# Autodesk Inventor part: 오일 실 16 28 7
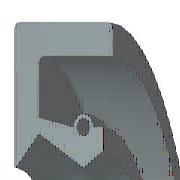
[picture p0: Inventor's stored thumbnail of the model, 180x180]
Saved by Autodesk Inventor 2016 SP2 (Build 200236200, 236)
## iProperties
Created: 2012-02
Part Number: 오일 실 16 28 7
Material: 고무
Description: 오일-실
Document SubType Name: Modeling
Standard: KS B 2804
Designer: mduedu
Standards Organization: KS
Language: ko-KR
Size Designation: D - 16 28 7
Categories: <MemberInstance><Categories><Category DisplayName="샤프트 부품" InternalName="7f7aeb1f-a693-4053-b835-cee3144e0d98" Mnemonic="SHFT"><Category DisplayName="실링" Intern
Density: 0.93 g/cm^3
Appearance: 고무 - 검은색 - 버전 1.1
IsCustomPart: 1
Author: mduedu
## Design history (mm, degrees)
revolve "본체" stored, may be unused: angle "d17" = 90 deg
revolve "스프링1" stored, may be unused: angle "d18" = 90 deg
fillet "모깎기3" dims "d43" = 0.5
body "Solid1"
sketch "스케치1"
  geometry: L1 (0, 14)-(7, 14); L2 (7, 12.25)-(1.75, 12.25); L3 (1.75, 9.75)-(4.9, 8); L4 (4.9, 8)-(0, 8); L5 (0, 0)-(9.586, 0) reference; L6 (4.9, 8)-(6.3, 8.875); L7 (0, 18)-(0, -3) reference; L8 (-1.941, 0)-(11.507, 0) reference; L9 (4.2, 10.1)-(1.75, 10.59); L10 (1.75, 10.59)-(1.75, 12.25); L11 (0, 14)-(0, 8.088); L12 (4.9, 8)-(0, 8); L13 (1.75, 9.75)-(0.152, 8.028); L14 (7, 14)-(7, 12.25); L15 (5.6, 10.1)-(6.3, 10.1); L16 (6.3, 10.1)-(6.3, 8.875); C1 r 0.455 at (4.9, 10.1); A1 r 0.7 centre (4.9, 10.1) between (5.6, 10.1) and (4.2, 10.1); A2 r 0.088 centre (0.088, 8.088) between (0, 8.088) and (0.152, 8.028); 1 further point
  constraints: 28 end point, 5 horizontal alignment, 5 point on line, 4 point on circle, 4 vertical alignment, 3 centre point, 3 tangent, 2 collinear, 2 horizontal, 2 perpendicular, 1 coincident, 1 parallel
  dimensions: "d0" = 28 diameter of L1 L5 (= SD2); "d1" = 1.75 distance of L1.end L2.start (= SD); "d2" = 0.91 diameter of C1 (= SPDI); "d3" = 1.4 diameter of A1 (= SPDA); "d4" = 16 diameter of L3.end L5 (= NND); "d5" = 19.5 diameter of L3.start L5 (= TKDM); "d7" = 21.18 diameter of L9.end L5 (= TKDM + 0.24 x SWDT); "d8" = 1.75 distance between parallel lines of L11 L10 (= SD); "d9" = 4.9 distance from line of L11 C1.centre (= SPDST); "d10" = 20.2 diameter of C1.centre L5 (= HLDM); "d11" = 0.0875 radius of A2 (= 0.25 x LAB); "d12" = 6.3 distance between parallel lines of L11 L16 (= SDI); "d13" = 17.75 diameter of L6.end L5 (= ABDM); "d14" = 7 distance from line of L11 L1.end (= SWDT)
fillet "모깎기1" dims "d6" = 0.3 (= RR)
other parameters: "SD2" = 28 [user parameter; used in 1 equation term], "SWDT" = 7 [user parameter; used in 2 equation terms], "RR" = 0.3 [user parameter; used in 1 equation term], "SD" = 1.75 [user parameter; used in 2 equation terms], "NND" = 16 [user parameter; used in 1 equation term], "SPDA" = 1.4 [user parameter; used in 1 equation term], "SPDI" = 0.91 [user parameter; used in 1 equation term], "TKDM" = 19.5 [user parameter; used in 2 equation terms], "HLDM" = 20.2 [user parameter; used in 1 equation term], "ABDM" = 17.75 [user parameter; used in 1 equation term], "SDI" = 6.3 [user parameter; used in 1 equation term], "SPDST" = 4.9 [user parameter; used in 1 equation term], "LAB" = 0.35 [user parameter; used in 1 equation term], "d15" = 0, "d16" = 0, "d19" = 0
